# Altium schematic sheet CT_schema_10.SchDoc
size 387 x 385 mm
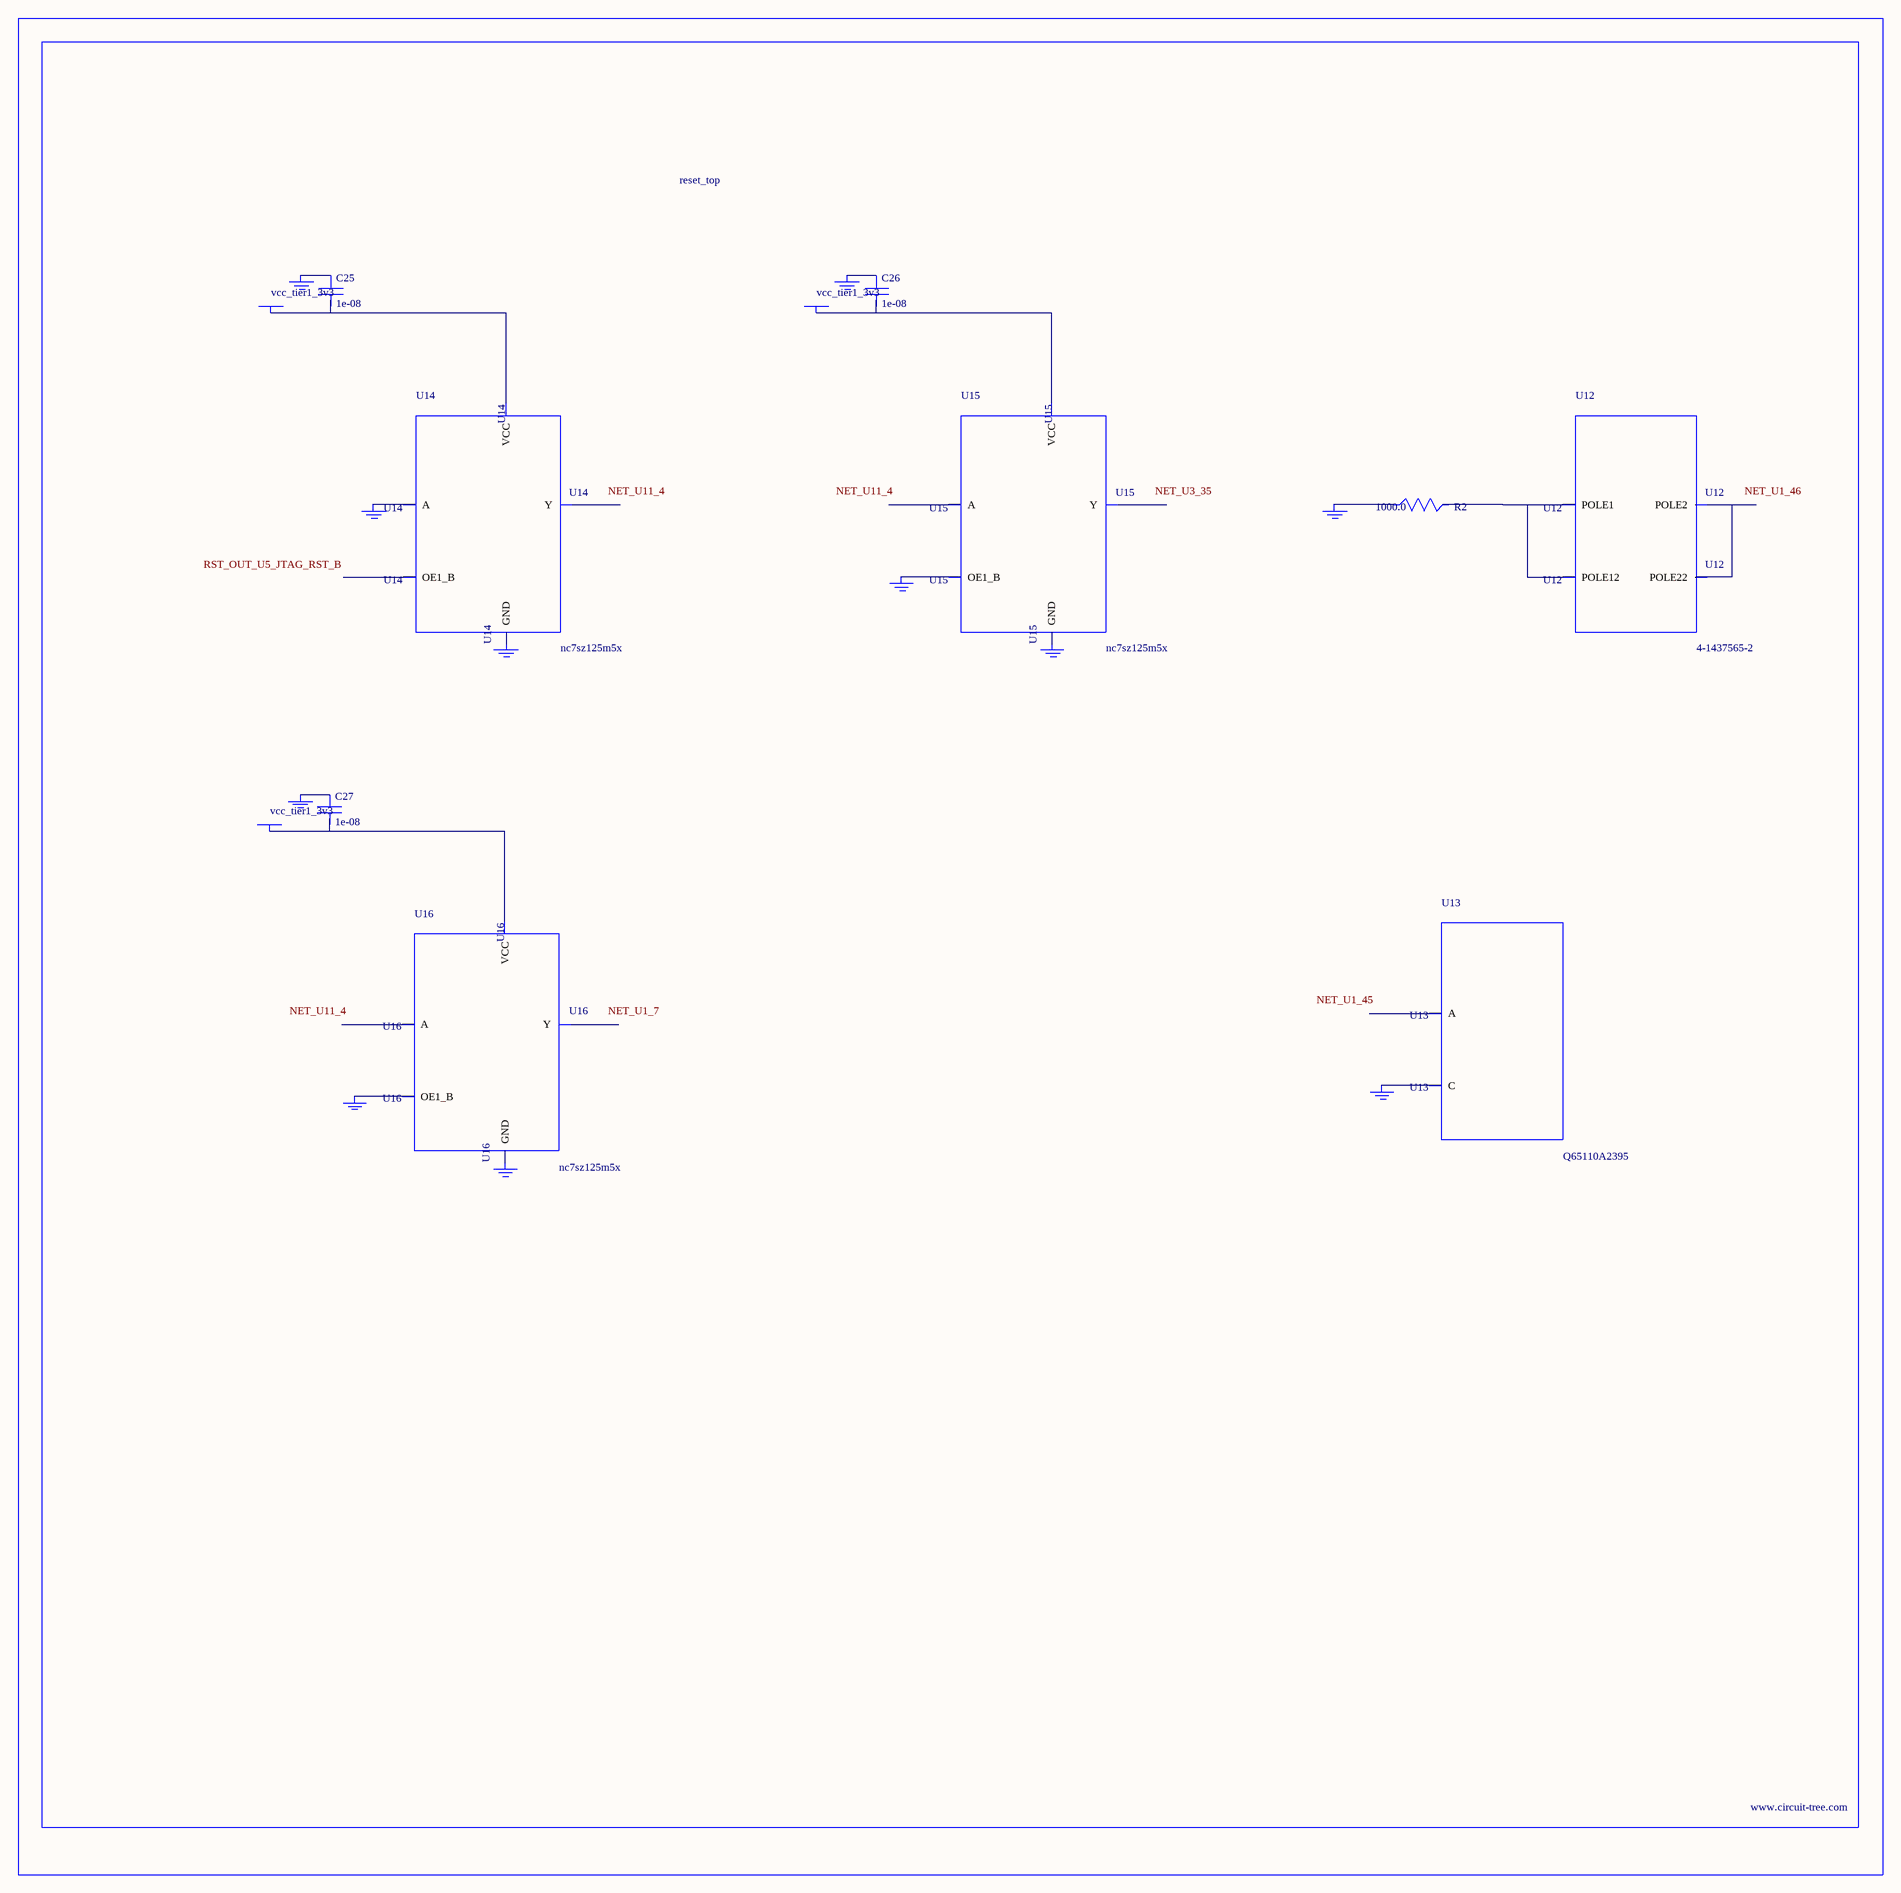
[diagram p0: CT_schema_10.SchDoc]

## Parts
BORDER9  (no value)
C25  1e-08  [C0402]
C26  1e-08  [C0402]
C27  1e-08  [C0402]
GND_INSTANCE_9_0  (no value)
GND_INSTANCE_9_1  (no value)
GND_INSTANCE_9_2  (no value)
GND_INSTANCE_9_3  (no value)
GND_INSTANCE_9_4  (no value)
GND_INSTANCE_9_5  (no value)
GND_INSTANCE_9_6  (no value)
GND_INSTANCE_9_7  (no value)
GND_INSTANCE_9_8  (no value)
GND_INSTANCE_9_9  (no value)
GND_INSTANCE_9_10  (no value)
POWER_INSTANCE_9_0  vcc_tier1_3v3
POWER_INSTANCE_9_1  vcc_tier1_3v3
POWER_INSTANCE_9_2  vcc_tier1_3v3
R2  1000.0  [R0603]
U12  4-1437565-2  [SW_4-1437565-2]
U13  Q65110A2395  [LGM67K-G1J2-24-Z]
U14  nc7sz125m5x  [NC7SZ125M5X]
U15  nc7sz125m5x  [NC7SZ125M5X]
U16  nc7sz125m5x  [NC7SZ125M5X]

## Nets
NetC25_1: C25.1 GND_INSTANCE_9_2.0(GND)
NetC25_2: C25.2 POWER_INSTANCE_9_0.0(PWR) U14.5(VCC)
NetC26_1: C26.1 GND_INSTANCE_9_5.0(GND)
NetC26_2: C26.2 POWER_INSTANCE_9_1.0(PWR) U15.5(VCC)
NetC27_1: C27.1 GND_INSTANCE_9_8.0(GND)
NetC27_2: C27.2 POWER_INSTANCE_9_2.0(PWR) U16.5(VCC)
NetGND_INSTANCE_9_0_0: GND_INSTANCE_9_0.0(GND) R2.1
NetGND_INSTANCE_9_1_0: GND_INSTANCE_9_1.0(GND) U13.C
NetGND_INSTANCE_9_3_0: GND_INSTANCE_9_3.0(GND) U14.2(A)
NetGND_INSTANCE_9_4_0: GND_INSTANCE_9_4.0(GND) U14.3(GND)
NetGND_INSTANCE_9_6_0: GND_INSTANCE_9_6.0(GND) U15.1(OE1_B)
NetGND_INSTANCE_9_7_0: GND_INSTANCE_9_7.0(GND) U15.3(GND)
NetGND_INSTANCE_9_9_0: GND_INSTANCE_9_9.0(GND) U16.1(OE1_B)
NetGND_INSTANCE_9_10_0: GND_INSTANCE_9_10.0(GND) U16.3(GND)
NetR2_2: R2.2 U12.1(POLE1) U12.2(POLE12)
NetU12_3: U12.3(POLE2) U12.4(POLE22)

Not connected (* = marked no-connect by the designer): U13 A; U14 1(OE1_B) 4(Y); U15 2(A) 4(Y); U16 2(A) 4(Y)

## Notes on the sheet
- Labels drawn without touching a wire or pin: NET_U1_7, NET_U1_45, NET_U1_46, NET_U3_35, NET_U11_4, RST_OUT_U5_JTAG_RST_B

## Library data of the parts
BORDER9 = BORDER_PAGE9
C25-C27 = C0402C103K3RAC
GND_INSTANCE_9_0-GND_INSTANCE_9_10 = GND
POWER_INSTANCE_9_0-POWER_INSTANCE_9_2 = PWR
R2 = RC0603JR-071KL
